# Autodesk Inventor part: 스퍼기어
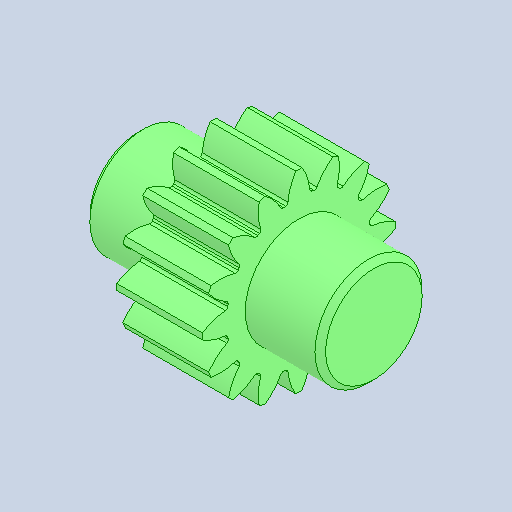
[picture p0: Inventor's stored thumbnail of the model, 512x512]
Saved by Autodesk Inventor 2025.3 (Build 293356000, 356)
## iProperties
Created: 2025-10
Part Number: 스퍼기어
Material: 강철, 합금
Document SubType Name: Modeling
Designer: PC-04
Density: 7.73 g/cm^3
Appearance: 기본값
Author: jhkim
Sending System: Autodesk Inventor 2026
Preprocessor: ST-DEVELOPER v20.1
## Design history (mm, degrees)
feature "솔리드1"
node "솔리드2"
